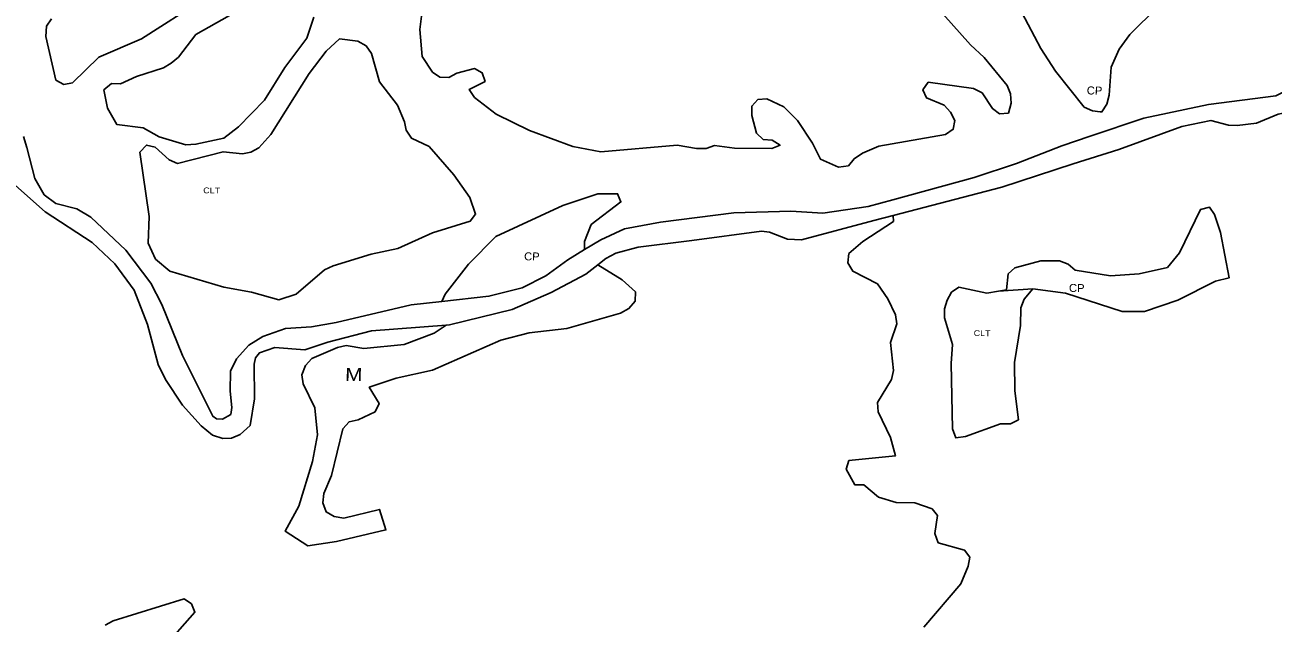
# Model space of a CAD drawing. Extents: x 713589 to 726391, y 7177764 to 7191819.
# Drawn here: x 717161 to 718159, y 7179057 to 7179535 of the extents above; entities that cross this region are included whole.
import ezdxf
from ezdxf.enums import TextEntityAlignment as Align

# ---------------------------------------------------------------- set-up
doc = ezdxf.new("R2010")
doc.units = 0
doc.header["$LTSCALE"] = 2.6
doc.layers.add('63', color=7, linetype='Continuous', lineweight=25)

msp = doc.modelspace()

# ---------------------------------------------------------------- linework, layer by layer
at = {"layer": '63'}
msp.add_line((717939.33, 7179322.13), (717966.56, 7179323.81), dxfattribs=at)
for points in [[(718066.55, 7179549.36), (718044.23, 7179527.37), (718035.69, 7179515.56), (718029.45, 7179501.12), (718027.81, 7179478.81), (718025.84, 7179471.59), (718021.9, 7179465.35), (718020.53, 7179465.53), (718014.35, 7179466.34), (718007.79, 7179469.29), (717984.82, 7179497.85), (717973.01, 7179516.23), (717932.66, 7179593.03)], [(717478.21, 7179546.1), (717476.23, 7179531.3), (717478.2, 7179509.58), (717486.42, 7179497.29), (717492.35, 7179493.12), (717499.59, 7179492.79), (717505.84, 7179496.41), (717520, 7179500.03), (717526.25, 7179496.74), (717528.55, 7179489.82), (717515.71, 7179483.25), (717519.99, 7179476.99), (717537.43, 7179463.5), (717564.08, 7179450.66), (717598.63, 7179437.82), (717621.01, 7179433.54), (717682.22, 7179438.79), (717697.68, 7179436.16), (717705.25, 7179436.15), (717712.16, 7179438.46), (717727.96, 7179436.48), (717757.9, 7179436.15), (717764.48, 7179438.78), (717758.23, 7179442.73), (717750.99, 7179443.39), (717745.73, 7179448.32), (717741.78, 7179462.47), (717741.78, 7179470.04), (717746.72, 7179475.31), (717753.96, 7179475.96), (717767.45, 7179469.38), (717778.31, 7179458.52), (717790.48, 7179440.42), (717796.73, 7179427.58), (717811.21, 7179421.33), (717819.11, 7179422.31), (717823.71, 7179427.91), (717830.3, 7179432.51), (717843.46, 7179438.11), (717896.77, 7179447.31), (717903.02, 7179451.59), (717904.34, 7179458.5), (717900.72, 7179465.08), (717895.79, 7179470.67), (717881.64, 7179476.6), (717878.68, 7179483.18), (717882.96, 7179489.1), (717919.15, 7179484.16), (717926.06, 7179480.54), (717934.29, 7179468.03), (717939.88, 7179463.76), (717947.12, 7179464.41), (717949.43, 7179472.31), (717948.77, 7179479.88), (717946.14, 7179486.46), (717927.71, 7179508.84), (717916.86, 7179519.04), (717874.74, 7179566.44)], [(717303.15, 7179555.68), (717253.78, 7179523.77), (717219.56, 7179509.29), (717198.49, 7179488.57), (717191.58, 7179487.25), (717185.33, 7179490.87), (717177.11, 7179525.75), (717177.77, 7179533.98), (717181.72, 7179539.9)], [(717391.66, 7179541.18), (717386.07, 7179524.4), (717368.29, 7179501.04), (717352.16, 7179474.72), (717331.43, 7179453.33), (717319.58, 7179444.45), (717297.2, 7179439.52), (717289.31, 7179439.19), (717267.92, 7179445.45), (717255.09, 7179452.69), (717234.03, 7179455.32), (717226.46, 7179468.49), (717223.5, 7179482.97), (717229.75, 7179488.23), (717236.99, 7179487.9), (717249.83, 7179493.82), (717271.22, 7179500.73), (717277.47, 7179504.35), (717283.4, 7179509.28), (717297.22, 7179527.38), (717324.21, 7179542.51)], [(717854.58, 7179395.17), (717919.62, 7179412.84), (717953.71, 7179424.1), (717989.86, 7179438.24), (718012.44, 7179445.87), (718055.5, 7179460.42), (718107.27, 7179471.36), (718161.03, 7179478.23), (718168.4, 7179481.98)], [(717855, 7179382.57), (717941.99, 7179405.15), (717998.88, 7179423.95), (718035.37, 7179435.38), (718085.72, 7179453.72), (718109.09, 7179458.41), (718123.22, 7179454.67), (718130.05, 7179454.57), (718145.63, 7179456.3), (718162.84, 7179463.57), (718169.83, 7179464.89), (718186.43, 7179468.03), (718201.94, 7179466.9)], [(717159.27, 7179445.79), (717161.91, 7179436.99), (717168.37, 7179412.18), (717175.84, 7179399.16), (717185.29, 7179392.15), (717202.04, 7179387.86), (717213.28, 7179381.3), (717241.24, 7179354.94), (717261.27, 7179328.51), (717270.11, 7179311.51), (717286.51, 7179270.64), (717310.85, 7179221.97), (717313.83, 7179219.94), (717318.53, 7179219.57), (717325.27, 7179223.54), (717326.1, 7179229.1), (717324.59, 7179242.17), (717324.96, 7179258.09), (717329.64, 7179267.99), (717339.53, 7179278.98), (717350.82, 7179285.74), (717368.9, 7179292.25), (717389.62, 7179293.49), (717409.33, 7179297.11), (717469.43, 7179310.99), (717493.86, 7179313.75)], [(717153.05, 7179406.54), (717176.7, 7179385.5), (717214.34, 7179360.93), (717232.34, 7179343.98), (717247.98, 7179322.77), (717258.63, 7179295.32), (717267.12, 7179263.28), (717272.9, 7179251.45), (717286.49, 7179230.78), (717301.33, 7179214.49), (717310.41, 7179207.02), (717318.69, 7179204.11), (717325.69, 7179204.55), (717332.77, 7179207.36), (717340.71, 7179214.68), (717344.02, 7179235.84), (717343.85, 7179263.56), (717345.03, 7179268.66), (717348.06, 7179272.77), (717360.33, 7179276.98), (717384.38, 7179275.19), (717402.85, 7179281.14), (717437.58, 7179290.39), (717497.35, 7179294.93)], [(717608.12, 7179355.32), (717608.16, 7179361.8), (717613.43, 7179375.29), (717637.13, 7179393.39), (717634.49, 7179399.97), (717618.7, 7179399.97), (717590.73, 7179390.43), (717537.08, 7179365.76), (717515.36, 7179343.72), (717496.6, 7179319.7), (717493.86, 7179313.75)], [(717608.12, 7179355.32), (717621.2, 7179363.22), (717639.99, 7179371.82), (717668.94, 7179377.25), (717727.61, 7179384.78), (717772.97, 7179386.1), (717798.61, 7179384.52), (717834.95, 7179389.83), (717854.58, 7179395.17)], [(717966.56, 7179323.81), (717992.71, 7179320.53), (718038.12, 7179305.72), (718055.88, 7179305.72), (718082.54, 7179314.92), (718112.82, 7179330.06), (718123.58, 7179332.67), (718116.77, 7179368.89), (718111.84, 7179383.37), (718107.89, 7179389.29), (718100.65, 7179387.32), (718083.86, 7179352.77), (718074.32, 7179340.92), (718051.61, 7179335.99), (718028.91, 7179334.35), (718000.61, 7179338.96), (717995.01, 7179343.57), (717988.1, 7179346.2), (717972.97, 7179346.21), (717952.23, 7179340.62), (717946.97, 7179336.01), (717945.65, 7179323.18), (717939.33, 7179322.13)], [(717618.77, 7179343.12), (717625.18, 7179348.1), (717633.24, 7179352.48), (717650.87, 7179357.16), (717693.82, 7179362.68), (717749.56, 7179370.05), (717755.98, 7179369.26), (717770.45, 7179363.5), (717781.57, 7179363.13), (717839.42, 7179378.53), (717855, 7179382.57)], [(717909.08, 7179087.9), (717915.01, 7179102.05), (717916.32, 7179109.29), (717912.05, 7179114.88), (717890.99, 7179120.81), (717888.36, 7179128.38), (717890.33, 7179142.53), (717886.06, 7179148.12), (717872.24, 7179152.73), (717857.43, 7179153.06), (717843.28, 7179157.34), (717831.43, 7179167.22), (717824.2, 7179167.22), (717817.29, 7179179.72), (717819.59, 7179186.63), (717856.78, 7179190.25), (717852.83, 7179205.06), (717842.96, 7179225.46), (717842.31, 7179233.03), (717853.5, 7179251.45), (717855.14, 7179258.69), (717852.84, 7179281.07), (717857.78, 7179295.88), (717856.8, 7179303.12), (717850.55, 7179315.95), (717842.32, 7179327.8), (717822.58, 7179338.01), (717818.63, 7179344.59), (717819.62, 7179352.16), (717830.81, 7179361.7), (717855.16, 7179377.82), (717855, 7179382.57)], [(717493.86, 7179313.75), (717531.56, 7179318.01), (717558.23, 7179324.71), (717577.14, 7179334.26), (717594.65, 7179347.19), (717608.12, 7179355.32)], [(717618.77, 7179343.12), (717638.3, 7179331.13), (717648.83, 7179321.58), (717648.5, 7179314.01), (717643.56, 7179308.09), (717636.98, 7179304.47), (717593.87, 7179292.3), (717563.92, 7179288.69), (717541.21, 7179282.77), (717486.58, 7179258.76), (717457.3, 7179252.51), (717435.91, 7179245.28), (717443.8, 7179232.11), (717440.51, 7179225.53), (717427.02, 7179219.28), (717419.78, 7179217.64), (717414.84, 7179212.04), (717405.62, 7179174.53), (717399.69, 7179160.38), (717398.7, 7179152.81), (717401.34, 7179145.57), (717407.92, 7179141.95), (717415.48, 7179140.63), (717444.12, 7179147.54), (717449.19, 7179131.16), (717409.69, 7179121.94), (717386.65, 7179118.33), (717368.7, 7179130.01), (717379.62, 7179150.18), (717390.48, 7179185.72), (717394.44, 7179207.11), (717392.47, 7179228.83), (717382.93, 7179247.92), (717381.94, 7179255.16), (717384.9, 7179262.73), (717389.84, 7179268.32), (717410.57, 7179276.87), (717417.48, 7179278.51), (717431.63, 7179276.21), (717463.88, 7179279.49), (717487.91, 7179288.37), (717497.35, 7179294.93)], [(717497.35, 7179294.93), (717500, 7179295.25), (717550.26, 7179307.51), (717581.29, 7179320.97), (717609.26, 7179335.74), (717618.77, 7179343.12)], [(717966.56, 7179323.81), (717959.8, 7179315.6), (717957.16, 7179308.69), (717956.83, 7179294.54), (717951.89, 7179264.93), (717952.22, 7179242.22), (717955.17, 7179219.19), (717948.92, 7179215.9), (717940.69, 7179215.9), (717912.72, 7179205.7), (717905.15, 7179204.72), (717902.52, 7179211.96), (717901.21, 7179264.28), (717902.53, 7179279.42), (717895.96, 7179300.81), (717895.96, 7179308.05), (717898.26, 7179314.96), (717901.55, 7179321.21), (717907.48, 7179325.16), (717929.85, 7179320.55), (717939.33, 7179322.13)], [(717879.46, 7179053.35), (717909.08, 7179087.9)], [(717224.74, 7179054.85), (717230.99, 7179058.47), (717287.93, 7179075.9), (717293.85, 7179071.95), (717296.48, 7179065.36), (717270.48, 7179036.08)]]:
    msp.add_lwpolyline(points, dxfattribs=at)
msp.add_lwpolyline([(717464.05, 7179457.59), (717458.45, 7179470.75), (717443.98, 7179489.51), (717437.73, 7179512.22), (717433.45, 7179518.14), (717426.87, 7179522.09), (717412.06, 7179523.74), (717401.53, 7179513.87), (717387.71, 7179496.1), (717357.1, 7179447.4), (717347.55, 7179436.55), (717341.3, 7179433.26), (717334.39, 7179431.94), (717318.92, 7179433.59), (717282.39, 7179424.05), (717275.81, 7179427.02), (717264.63, 7179437.22), (717257.72, 7179438.87), (717252.45, 7179433.27), (717259.95, 7179381.63), (717259.02, 7179360.55), (717264.94, 7179347.71), (717276.45, 7179338.17), (717319.56, 7179325.33), (717341.61, 7179321.37), (717363.65, 7179315.12), (717377.48, 7179319.72), (717400.19, 7179339.13), (717407.1, 7179342.42), (717437.37, 7179351.63), (717458.76, 7179356.23), (717486.41, 7179368.73), (717516.68, 7179377.94), (717520.96, 7179383.54), (717516.36, 7179397.03), (717503.53, 7179415.13), (717483.79, 7179437.84), (717469.64, 7179444.42), (717465.36, 7179450.68)], close=True, dxfattribs=at)

# ---------------------------------------------------------------- texts
for s, height, width, p in [('CP', 6.4, 1.05, (718016.01, 7179479.29)), ('CLT', 4.64, 1.15, (717309.79, 7179400.24)), ('CP', 6.4, 1.05, (717565.93, 7179346.63)), ('CP', 6.4, 1.05, (718001.76, 7179321.36)), ('CLT', 4.64, 1.15, (717926.08, 7179286.11)), ('M', 10.4, 1.2, (717423.45, 7179250.18))]:
    msp.add_text(s, height=height, rotation=359.062, dxfattribs=dict(at, width=width)).set_placement(p, align=Align.CENTER)

doc.saveas('drawing.dxf')
